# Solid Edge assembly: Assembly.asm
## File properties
Author: Administrator
Template: Normal.asm
Last saved by: Cadcim
Revision: 6
Application: Solid Edge
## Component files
Stock_support_base.par
thrust_bearing.par
adjusting_screw_nut.par
support_adjusting_screw.par
support_roller_bracket.par
stock_support_roller.par
adjusting_nut_handle.par
adjusting_screw_guide.par
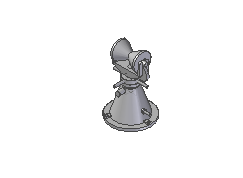
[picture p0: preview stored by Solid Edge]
